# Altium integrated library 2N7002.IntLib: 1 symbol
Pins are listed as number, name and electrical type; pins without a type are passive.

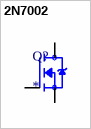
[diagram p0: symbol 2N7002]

## 2N7002
designator Q?
N-Channel 60V 280mA (Ta) 350mW (Ta) Surface Mount SOT-23-3 (TO-236); MP: altium_native_batch
footprint SOT95P240X111-3N
pins: 1 G, 2 S, 3 D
